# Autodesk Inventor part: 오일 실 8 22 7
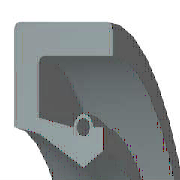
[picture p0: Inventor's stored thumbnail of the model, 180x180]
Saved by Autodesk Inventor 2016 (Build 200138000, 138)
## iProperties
IsCustomPart: 1
Created: 2012-02
Part Number: 오일 실 8 22 7
Material: 고무
Description: 오일-실
Document SubType Name: Modeling
Standard: KS B 2804
Designer: test
Standards Organization: KS
Language: ko-KR
Size Designation: S - 8 22 7
Categories: <MemberInstance><Categories><Category DisplayName="샤프트 부품" InternalName="7f7aeb1f-a693-4053-b835-cee3144e0d98" Mnemonic="SHFT"><Category DisplayName="실링" Intern
Density: 0.93 g/cm^3
Appearance: 고무 - 검은색 - 버전 1.1
Mass: 1.07912 g
Surface Area: 17.6852 cm^2
Volume: 1.16034 cm^3
Author: test
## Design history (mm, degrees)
revolve "본체" stored, may be unused: angle "d17" = 90 deg
revolve "스프링1" stored, may be unused: angle "d18" = 90 deg
body "Solid1"
sketch "스케치1"
  geometry: L1 (0, 11)-(7, 11); L2 (7, 11)-(7, 9.75); L3 (7, 9.75)-(1.75, 9.75); L4 (0, 11)-(0, 6.1); L5 (0, 6.1)-(1.75, 5.75); L6 (1.75, 5.75)-(4.9, 4); L7 (4.9, 4)-(0, 4); L8 (6.3, 4.875)-(6.3, 6.1); L9 (0, 0)-(9.586, 0) reference; L10 (4.9, 4)-(6.3, 4.875); L11 (0, 18)-(0, -3) reference; L12 (-1.917, 0)-(11.503, 0) reference; L13 (4.2, 6.1)-(1.75, 6.59); L14 (1.75, 6.59)-(1.75, 9.75); L15 (6.3, 6.1)-(5.6, 6.1); C1 r 0.455 at (4.9, 6.1); A1 r 0.7 centre (4.9, 6.1) between (5.6, 6.1) and (4.2, 6.1)
  constraints: 26 end point, 5 horizontal alignment, 4 perpendicular, 2 centre point, 2 collinear, 2 horizontal, 2 parallel, 2 point on circle, 2 point on line, 2 vertical alignment, 1 coincident
  dimensions: "d0" = 22 diameter of L1 L9 (= SD2); "d1" = 9.75 diameter of L8.start L9 (= ABDM); "d2" = 1.25 distance of L1.end L2.end (computed from SD); "d3" = 0.91 diameter of C1 (= SPDI); "d4" = 1.4 diameter of A1 (= SPDA); "d5" = 8 diameter of L6.end L9 (= NND); "d6" = 11.5 diameter of L5.end L9 (= TKDM); "d7" = 12.2 diameter of L4.end L9 (= HLDM); "d8" = 4.9 distance from line of C1.centre L4 (= SPDST); "d9" = 6.3 distance between parallel lines of L8 L4 (= SDI); "d10" = 7 distance between parallel lines of L2 L4 (= SWDT); "d12" = 1.75 distance between parallel lines of L14 L4 (= SD)
fillet "모깎기1" dims "d11" = 0.3 (= RR)
other parameters: "SD2" = 22 [user parameter; used in 1 equation term], "SWDT" = 7 [user parameter; used in 1 equation term], "RR" = 0.3 [user parameter; used in 1 equation term], "SD" = 1.75 [user parameter; used in 2 equation terms], "NND" = 8 [user parameter; used in 1 equation term], "SPDA" = 1.4 [user parameter; used in 1 equation term], "SPDI" = 0.91 [user parameter; used in 1 equation term], "TKDM" = 11.5 [user parameter; used in 1 equation term], "HLDM" = 12.2 [user parameter; used in 1 equation term], "ABDM" = 9.75 [user parameter; used in 1 equation term], "SDI" = 6.3 [user parameter; used in 1 equation term], "SPDST" = 4.9 [user parameter; used in 1 equation term], "d13" = 0, "d14" = 0, "d15" = 0, "LAB" = 0.35 [user parameter]
